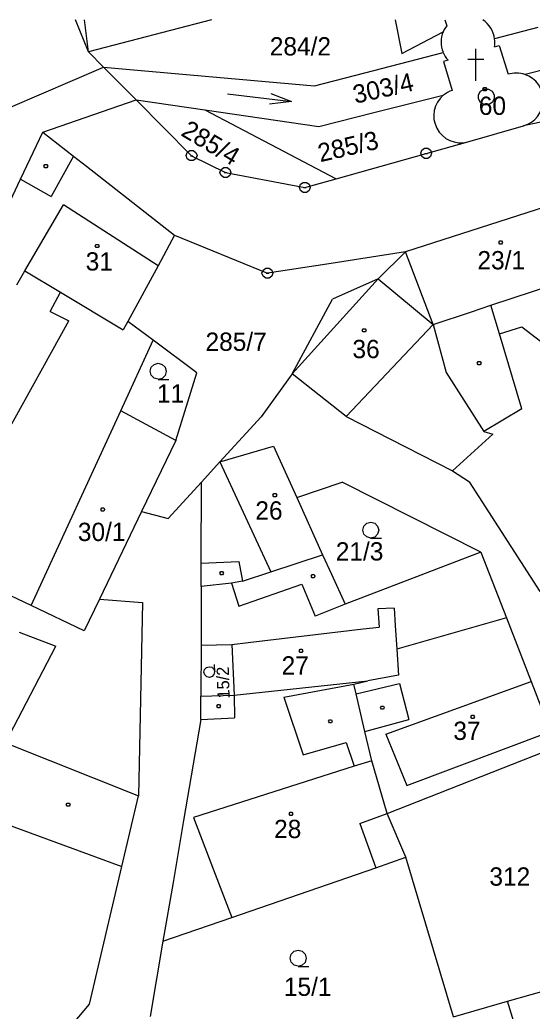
# Model space of a CAD drawing. Extents: x -779723 to -777378, y -1011169 to -1009297.
# Drawn here: x -779184 to -779136.4, y -1010377.2 to -1010285.1 of the extents above; entities that cross this region are included whole.
import ezdxf

# ---------------------------------------------------------------- set-up
doc = ezdxf.new("R2010")
doc.units = 0
for name, color, linetype in [('Default', 7, 'Continuous'), ('KN_HRANICE', 7, 'Continuous'), ('KN_KULTURY', 7, 'Continuous'), ('KN_PARCELY', 7, 'Continuous'), ('KN_SLUCKY', 7, 'Continuous')]:
    doc.layers.add(name, color=color, linetype=linetype)

# ---------------------------------------------------------------- blocks, each defined once
blk = doc.blocks.new('101')
at = {"layer": 'Default'}
blk.add_line((-0.05, 0), (0.05, 0), dxfattribs=at)
blk.add_lwpolyline([(0.19, 0.72), (0.53, 0.53), (0.72, 0.19), (0.72, -0.2), (0.53, -0.54), (0.19, -0.73), (-0.2, -0.73), (-0.54, -0.54), (-0.73, -0.2), (-0.73, 0.19), (-0.54, 0.53), (-0.2, 0.72), (0.19, 0.72)], dxfattribs=at)
blk = doc.blocks.new('304')
at = {"layer": 'Default'}
blk.add_lwpolyline([(0, 0), (-0.38, 0.1), (-0.65, 0.37), (-0.75, 0.74), (-0.65, 1.11), (-0.38, 1.38), (-0.01, 1.48), (0.36, 1.38), (0.63, 1.11), (0.73, 0.73), (0.63, 0.35), (0.36, 0.08), (-0.02, -0.02), (0.98, -0.02)], dxfattribs=at)
blk = doc.blocks.new('802')
at = {"layer": 'Default'}
blk.add_line((-3, 0), (3, 0), dxfattribs=at)
blk.add_lwpolyline([(1, 0.5), (3, 0), (1, -0.5)], dxfattribs=at)
blk = doc.blocks.new('402')
at = {"layer": 'Default'}
blk.add_lwpolyline([(0.09, 0.15), (0.18, 0), (0.09, -0.15), (-0.09, -0.15), (-0.18, 0), (-0.09, 0.15), (0.09, 0.15)], dxfattribs=at)
blk = doc.blocks.new('4091')
at = {"layer": 'Default'}
for p, q in [((0, 0), (0, 3)), ((0.75, 2), (-0.75, 2))]:
    blk.add_line(p, q, dxfattribs=at)
blk = doc.blocks.new('105')
at = {"layer": 'Default'}
blk.add_line((-0.12, 0), (0.12, 0), dxfattribs=at)
blk.add_lwpolyline([(0.15, 0.48), (0.4, 0.3), (0.5, 0.01), (0.4, -0.28), (0.15, -0.46), (-0.16, -0.46), (-0.41, -0.28), (-0.51, 0.01), (-0.41, 0.3), (-0.16, 0.48), (0.15, 0.48)], dxfattribs=at)

msp = doc.modelspace()

# ---------------------------------------------------------------- linework, layer by layer
at = {"layer": 'KN_HRANICE'}
for p, q in [((-779177.62, -1010288.07), (-779178.823, -1010285.087)), ((-779166.174, -1010285.087), (-779177.62, -1010288.07)), ((-779149.11, -1010285.087), (-779148.5, -1010288.21)), ((-779144.494, -1010285.087), (-779144.33, -1010285.63)), ((-779135.87, -1010285.81), (-779139.88, -1010286.86)), ((-779148.5, -1010288.21), (-779144.67, -1010286.2)), ((-779139.9, -1010287.6), (-779139.45, -1010287.47)), ((-779139.45, -1010287.47), (-779138.64, -1010290.15)), ((-779177.62, -1010288.07), (-779176.23, -1010289.47)), ((-779151.93, -1010290), (-779144.67, -1010288.11)), ((-779184.85, -1010293.19), (-779176.23, -1010289.47)), ((-779176.23, -1010289.47), (-779173.19, -1010292.52)), ((-779176.23, -1010289.47), (-779156.62, -1010291.23)), ((-779144.21, -1010288.84), (-779144.64, -1010288.96)), ((-779144.64, -1010288.96), (-779143.83, -1010291.64)), ((-779134.73, -1010289.57), (-779137.06, -1010290.16)), ((-779156.62, -1010291.23), (-779151.93, -1010290)), ((-779150.97, -1010293.68), (-779144.65, -1010292.08)), ((-779181.85, -1010295.53), (-779173.19, -1010292.52)), ((-779173.19, -1010292.52), (-779168.03, -1010297.71)), ((-779173.19, -1010292.52), (-779166.79, -1010293.46)), ((-779127.4, -1010292.89), (-779137.19, -1010294.93)), ((-779166.79, -1010293.46), (-779156.22, -1010295.01)), ((-779166.79, -1010293.46), (-779154.6, -1010299.85)), ((-779156.22, -1010295.01), (-779150.97, -1010293.68)), ((-779142.38, -1010296.42), (-779137.19, -1010294.93)), ((-779183.92, -1010299.88), (-779181.85, -1010295.53)), ((-779181.85, -1010295.53), (-779179.01, -1010297.75)), ((-779146.24, -1010297.5), (-779142.38, -1010296.42)), ((-779179.01, -1010297.75), (-779177.81, -1010298.69)), ((-779168.03, -1010297.71), (-779164.89, -1010299.28)), ((-779154.6, -1010299.85), (-779146.24, -1010297.5)), ((-779177.81, -1010298.69), (-779169.61, -1010305.1)), ((-779164.89, -1010299.28), (-779157.51, -1010300.67)), ((-779187.65, -1010307.74), (-779183.92, -1010299.88)), ((-779157.51, -1010300.67), (-779154.6, -1010299.85)), ((-779133.45, -1010301.92), (-779148.16, -1010306.65)), ((-779169.61, -1010305.1), (-779171.15, -1010307.94)), ((-779169.61, -1010305.1), (-779160.99, -1010308.63)), ((-779150.7, -1010309.16), (-779148.16, -1010306.65)), ((-779145.58, -1010313.4), (-779148.16, -1010306.65)), ((-779171.15, -1010307.94), (-779173.96, -1010313.1)), ((-779184.27, -1010309.7), (-779183.51, -1010308.4)), ((-779183.51, -1010308.4), (-779180.21, -1010310.38)), ((-779150.7, -1010309.16), (-779154.94, -1010311.03)), ((-779180.21, -1010310.38), (-779174.39, -1010313.89)), ((-779158.7, -1010317.98), (-779154.94, -1010311.03)), ((-779142.02, -1010312.21), (-779140.22, -1010311.61)), ((-779139.43, -1010314.26), (-779140.22, -1010311.61)), ((-779145.58, -1010313.4), (-779142.02, -1010312.21)), ((-779173.96, -1010313.1), (-779174.39, -1010313.89)), ((-779171.61, -1010314.85), (-779173.96, -1010313.1)), ((-779145.58, -1010313.4), (-779144.39, -1010317.86)), ((-779139.43, -1010314.26), (-779137.34, -1010313.6)), ((-779137.34, -1010313.6), (-779130.26, -1010319.11)), ((-779174.62, -1010321.41), (-779171.61, -1010314.85)), ((-779167.55, -1010317.87), (-779171.61, -1010314.85)), ((-779169.49, -1010324.18), (-779167.55, -1010317.87)), ((-779158.7, -1010317.98), (-779161.56, -1010321.97)), ((-779153.68, -1010321.94), (-779158.7, -1010317.98)), ((-779144.39, -1010317.86), (-779140.88, -1010323.34)), ((-779169.49, -1010324.18), (-779174.62, -1010321.41)), ((-779165.4, -1010326.16), (-779161.56, -1010321.97)), ((-779153.68, -1010321.94), (-779148.16, -1010324.76)), ((-779143.8, -1010326.98), (-779140.06, -1010323.57)), ((-779140.88, -1010323.34), (-779140.06, -1010323.57)), ((-779169.49, -1010324.18), (-779172.68, -1010330.78)), ((-779165.4, -1010326.16), (-779160.41, -1010324.71)), ((-779160.41, -1010324.71), (-779158.26, -1010329.46)), ((-779148.16, -1010324.76), (-779143.8, -1010326.98)), ((-779167.12, -1010328.04), (-779165.4, -1010326.16)), ((-779143.8, -1010326.98), (-779142.22, -1010328.02)), ((-779170.22, -1010331.41), (-779167.12, -1010328.04)), ((-779167.14, -1010335.56), (-779167.12, -1010328.04)), ((-779158.26, -1010329.46), (-779154.05, -1010328.04)), ((-779141.16, -1010334.55), (-779154.05, -1010328.04)), ((-779135.65, -1010338.2), (-779142.22, -1010328.02)), ((-779158.26, -1010329.46), (-779155.86, -1010334.78)), ((-779172.68, -1010330.78), (-779176.6, -1010338.9)), ((-779172.68, -1010330.78), (-779170.22, -1010331.41)), ((-779182.94, -1010339.51), (-779193.43, -1010334.55)), ((-779160.66, -1010336.36), (-779155.86, -1010334.78)), ((-779155.86, -1010334.78), (-779155.05, -1010336.58)), ((-779141.16, -1010334.55), (-779153.78, -1010339.39)), ((-779141.16, -1010334.55), (-779138.79, -1010340.66)), ((-779167.14, -1010337.72), (-779167.14, -1010335.56)), ((-779163.3, -1010337.23), (-779160.66, -1010336.36)), ((-779155.05, -1010336.58), (-779153.78, -1010339.39)), ((-779164.32, -1010337.41), (-779167.14, -1010337.72)), ((-779163.3, -1010337.23), (-779164.32, -1010337.41)), ((-779167.14, -1010337.72), (-779167.15, -1010343.18)), ((-779176.6, -1010338.9), (-779178.02, -1010341.84)), ((-779176.6, -1010338.9), (-779172.6, -1010339.21)), ((-779172.6, -1010339.21), (-779172.96, -1010357.18)), ((-779178.02, -1010341.84), (-779182.94, -1010339.51)), ((-779138.79, -1010340.66), (-779148.98, -1010343.57)), ((-779138.79, -1010340.66), (-779136.5, -1010346.55)), ((-779167.15, -1010343.18), (-779167.16, -1010347.93)), ((-779167.15, -1010343.18), (-779164.31, -1010343.12)), ((-779164.31, -1010343.12), (-779164.08, -1010347.83)), ((-779148.98, -1010343.57), (-779148.82, -1010345.98)), ((-779164.08, -1010347.83), (-779151.66, -1010346.5)), ((-779152.96, -1010346.81), (-779151.66, -1010346.5)), ((-779148.82, -1010345.98), (-779151.66, -1010346.5)), ((-779136.5, -1010346.55), (-779134.69, -1010351.21)), ((-779152.75, -1010347.71), (-779152.96, -1010346.81)), ((-779167.17, -1010350.08), (-779167.16, -1010347.93)), ((-779167.16, -1010347.93), (-779164.08, -1010347.83)), ((-779151.93, -1010351.2), (-779152.75, -1010347.71)), ((-779167.17, -1010350.08), (-779168.77, -1010359.47)), ((-779151.29, -1010353.93), (-779151.93, -1010351.2)), ((-779149.85, -1010358.82), (-779134.14, -1010352.63)), ((-779149.85, -1010358.82), (-779151.29, -1010353.93)), ((-779174.51, -1010363.75), (-779172.96, -1010357.18)), ((-779187.61, -1010358.93), (-779174.51, -1010363.75)), ((-779168.77, -1010359.47), (-779169.76, -1010365.24)), ((-779148.14, -1010362.87), (-779149.85, -1010358.82)), ((-779150.92, -1010363.88), (-779148.14, -1010362.87)), ((-779143.7, -1010377.71), (-779148.14, -1010362.87)), ((-779177.51, -1010376.54), (-779174.51, -1010363.75)), ((-779164.31, -1010368.5), (-779150.92, -1010363.88)), ((-779169.76, -1010365.24), (-779170.69, -1010370.7)), ((-779170.69, -1010370.7), (-779164.31, -1010368.5)), ((-779170.69, -1010370.7), (-779171.88, -1010377.7)), ((-779138.68, -1010376.27), (-779126.96, -1010372.9)), ((-779181.94, -1010381.76), (-779177.51, -1010376.54)), ((-779143.7, -1010377.71), (-779138.68, -1010376.27))]:
    msp.add_line(p, q, dxfattribs=at)
msp.add_lwpolyline([(-779148.16, -1010306.65), (-779155.46, -1010307.78), (-779160.99, -1010308.63)], dxfattribs=at)
for centre, radius, start, end in [((-779142.11, -1010287.34), 2.8, 142.37447, 155.99411), ((-779142.38, -1010287.18), 2.52, 7.20294, 56.1589), ((-779142.41, -1010287.15), 2.45, 157.06637, 202.93363), ((-779142.16, -1010287.17), 2.3, 349.18761, 7.71608), ((-779142.3, -1010287.13), 2.56, 202.52776, 221.90533), ((-779137.87, -1010292.59), 2.56, 71.65557, 107.61918), ((-779137.87, -1010292.52), 2.5, 285.7463, 71.13143), ((-779143.03, -1010294), 2.51, 130.23724, 284.98563), ((-779142.99, -1010294.19), 2.68, 108.23221, 128.2025)]:
    msp.add_arc(centre, radius, start, end, dxfattribs=at)
at = {"layer": 'KN_SLUCKY'}
for p, q in [((-779177.62, -1010288.07), (-779177.974, -1010285.087)), ((-779179.01, -1010297.75), (-779181.08, -1010301.49)), ((-779183.92, -1010299.88), (-779181.08, -1010301.49)), ((-779183.51, -1010308.4), (-779179.93, -1010302.29)), ((-779171.15, -1010307.94), (-779179.93, -1010302.29)), ((-779140.22, -1010311.61), (-779131.16, -1010308.58)), ((-779158.7, -1010317.98), (-779150.7, -1010309.16)), ((-779150.7, -1010309.16), (-779145.58, -1010313.4)), ((-779181.18, -1010312.2), (-779180.21, -1010310.38)), ((-779181.18, -1010312.2), (-779179.44, -1010313.05)), ((-779185.22, -1010323.51), (-779179.44, -1010313.05)), ((-779153.68, -1010321.94), (-779145.58, -1010313.4)), ((-779137.35, -1010321.23), (-779139.43, -1010314.26)), ((-779182.94, -1010339.51), (-779174.62, -1010321.41)), ((-779137.35, -1010321.23), (-779140.88, -1010323.34)), ((-779165.4, -1010326.16), (-779160.66, -1010336.36)), ((-779167.14, -1010335.56), (-779163.63, -1010335.4)), ((-779163.63, -1010335.4), (-779163.3, -1010337.23)), ((-779164.32, -1010337.41), (-779163.63, -1010339.56)), ((-779163.63, -1010339.56), (-779157.78, -1010337.53)), ((-779157.78, -1010337.53), (-779156.56, -1010340.49)), ((-779153.78, -1010339.39), (-779156.56, -1010340.49)), ((-779149.23, -1010339.75), (-779150.73, -1010339.81)), ((-779150.73, -1010339.81), (-779150.61, -1010341.52)), ((-779149.23, -1010339.75), (-779149.12, -1010341.37)), ((-779184.06, -1010341.97), (-779180.63, -1010343.29)), ((-779162.78, -1010342.94), (-779152.1, -1010341.68)), ((-779152.1, -1010341.68), (-779150.61, -1010341.52)), ((-779149.12, -1010341.37), (-779148.98, -1010343.57)), ((-779164.31, -1010343.12), (-779162.78, -1010342.94)), ((-779185.33, -1010352.25), (-779180.63, -1010343.29)), ((-779152.75, -1010347.71), (-779148.71, -1010346.75)), ((-779149.98, -1010351.45), (-779136.5, -1010346.55)), ((-779148.71, -1010346.75), (-779147.85, -1010350.1)), ((-779159.47, -1010348.01), (-779152.96, -1010346.81)), ((-779164.08, -1010347.83), (-779164.04, -1010349.95)), ((-779159.47, -1010348.01), (-779157.66, -1010353.36)), ((-779167.17, -1010350.08), (-779164.04, -1010349.95)), ((-779151.93, -1010351.2), (-779147.85, -1010350.1)), ((-779148.04, -1010356.21), (-779134.69, -1010351.21)), ((-779185.33, -1010352.25), (-779172.96, -1010357.18)), ((-779157.66, -1010353.36), (-779153.67, -1010352.23)), ((-779153.67, -1010352.23), (-779152.93, -1010354.43)), ((-779149.98, -1010351.45), (-779148.04, -1010356.21)), ((-779151.29, -1010353.93), (-779152.93, -1010354.43)), ((-779152.93, -1010354.43), (-779167.87, -1010359.19)), ((-779167.87, -1010359.19), (-779166.01, -1010364.05)), ((-779152.41, -1010359.76), (-779149.85, -1010358.82)), ((-779152.41, -1010359.76), (-779150.92, -1010363.88)), ((-779166.01, -1010364.05), (-779164.31, -1010368.5)), ((-779136.94, -1010381.93), (-779138.68, -1010376.27))]:
    msp.add_line(p, q, dxfattribs=at)

# ---------------------------------------------------------------- block references
at = {"layer": 'KN_KULTURY'}
for name, p in [('4091', (-779141.62, -1010290.77)), ('402', (-779140.79, -1010291.53)), ('402', (-779181.57, -1010298.69)), ('402', (-779176.81, -1010306.1)), ('402', (-779139.32, -1010305.78)), ('402', (-779152, -1010313.94)), ('304', (-779171.13, -1010318.48)), ('402', (-779141.32, -1010316.99)), ('402', (-779160.31, -1010329.25)), ('402', (-779176.29, -1010330.58)), ('304', (-779151.38, -1010333.23)), ('402', (-779165.24, -1010336.5)), ('402', (-779156.75, -1010336.78)), ('402', (-779157.87, -1010343.72)), ('402', (-779165.52, -1010348.85)), ('402', (-779150.31, -1010348.99)), ('402', (-779155.14, -1010350.26)), ('402', (-779141.92, -1010349.85)), ('402', (-779179.49, -1010358)), ('402', (-779158.8, -1010358.86)), ('304', (-779158.12, -1010373.01))]:
    msp.add_blockref(name, p, dxfattribs=at)
at = {"layer": 'KN_KULTURY', "rotation": -6.9434070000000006}
msp.add_blockref('802', (-779161.73, -1010292.32), dxfattribs=at)
at = {"layer": 'KN_KULTURY', "xscale": 0.67, "yscale": 0.67, "rotation": 92.87645899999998}
msp.add_blockref('304', (-779165.9, -1010345.65), dxfattribs=at)
at = {"layer": 'KN_PARCELY'}
for name, p in [('101', (-779140.64, -1010292.24)), ('105', (-779146.24, -1010297.5)), ('105', (-779168.03, -1010297.71)), ('105', (-779164.89, -1010299.28)), ('105', (-779157.51, -1010300.67)), ('105', (-779160.99, -1010308.63))]:
    msp.add_blockref(name, p, dxfattribs=at)

# ---------------------------------------------------------------- texts
for s, p in [('284/2', (-779160.77, -1010288.4)), ('60', (-779141.35, -1010293.92)), ('31', (-779177.87, -1010308.38)), ('23/1', (-779141.48, -1010308.27)), ('285/7', (-779166.74, -1010315.84)), ('36', (-779153.09, -1010316.52)), ('11', (-779171.25, -1010320.64)), ('26', (-779162.109, -1010331.52)), ('30/1', (-779178.6, -1010333.51)), ('21/3', (-779154.639, -1010335.32)), ('27', (-779159.669, -1010345.92)), ('37', (-779143.719, -1010351.99)), ('28', (-779160.369, -1010361.11)), ('312', (-779140.369, -1010365.53)), ('15/1', (-779159.46, -1010375.77))]:
    msp.add_text(s, height=1.7, dxfattribs=at).set_placement(p)
for s, height, rotation, p in [('303/4', 1.7, 12.72, (-779152.83, -1010292.89)), ('285/4', 1.7, 329.164, (-779169.12, -1010295.78)), ('285/3', 1.7, 13.063, (-779156.08, -1010298.32)), ('15/2', 1.14, 91.616, (-779164.495, -1010348.136))]:
    msp.add_text(s, height=height, rotation=rotation, dxfattribs=at).set_placement(p)

doc.saveas('drawing.dxf')
